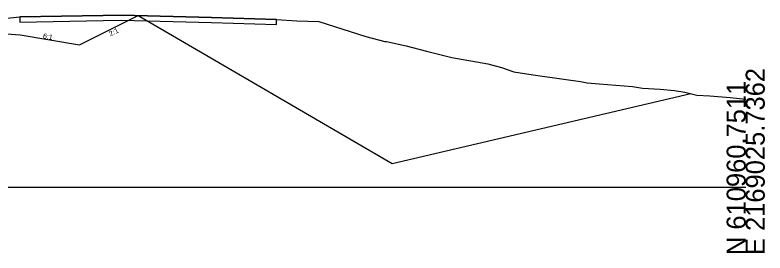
# Model space of a CAD drawing. Extents: x -26 to 1303, y -3010 to 12033.
# Drawn here: x 1192.5 to 1302.8, y 8990.3 to 9025.3 of the extents above; entities that cross this region are included whole.
import ezdxf

# ---------------------------------------------------------------- set-up
doc = ezdxf.new("R2010")
doc.units = 0
for name, color, linetype in [('RD_GPK_XS_Cell', 7, 'Continuous'), ('RD_Sketch10', 7, 'Continuous'), ('RD_XS_ExGround', 7, 'Continuous'), ('RD_XS_ExPaveRet', 7, 'Continuous'), ('RD_XS_Greenside', 7, 'Continuous'), ('RD_XS_TieSlope', 7, 'Continuous'), ('RD_XS_TX_Slope', 7, 'Continuous')]:
    doc.layers.add(name, color=color, linetype=linetype)

msp = doc.modelspace()

# ---------------------------------------------------------------- linework, layer by layer
at = {"layer": 'RD_GPK_XS_Cell'}
msp.add_line((1150, 9000), (1300, 9000), dxfattribs=at)
at = {"layer": 'RD_Sketch10'}
msp.add_lwpolyline([(1210.65, 9025.2), (1248.02, 9003.44), (1291.93, 9013.73)], dxfattribs=at)
at = {"layer": 'RD_XS_ExGround'}
msp.add_lwpolyline([(1186.62, 9024.32), (1193.26, 9024.98), (1205.52, 9025.21), (1208.25, 9025.26), (1221.44, 9024.91), (1230.99, 9024.63), (1233.96, 9024.42), (1237.23, 9024.31), (1244.12, 9022.13), (1246.91, 9021.36), (1247.15, 9021.36), (1250.05, 9020.73), (1253.07, 9019.97), (1256.77, 9019.02), (1262.09, 9018.09), (1264.08, 9017.56), (1265.88, 9016.94), (1268.74, 9016.5), (1273.23, 9015.82), (1275.69, 9015.5), (1276.68, 9015.28), (1278.46, 9015.18), (1283.36, 9014.76), (1284.82, 9014.5), (1287.42, 9014.38), (1289.52, 9014.17), (1291.06, 9013.95), (1292.81, 9013.5), (1294.74, 9013.4), (1297.74, 9013.13), (1300, 9012.91)], dxfattribs=at)
at = {"layer": 'RD_XS_ExPaveRet'}
for points in [[(1230.99, 9024.63), (1221.44, 9024.91), (1221.44, 9024.91), (1208.25, 9025.26), (1208.25, 9025.26), (1208.25, 9025.26), (1205.52, 9025.21), (1205.52, 9025.21), (1193.26, 9024.98), (1193.26, 9024.98), (1193.26, 9024.98), (1193.26, 9024.23), (1193.26, 9024.23), (1205.52, 9024.46), (1205.52, 9024.46), (1208.25, 9024.51), (1208.25, 9024.51), (1208.25, 9024.51), (1221.44, 9024.16), (1221.44, 9024.16), (1230.99, 9023.88), (1230.99, 9023.88), (1230.99, 9024.63), (1230.99, 9024.63), (1230.99, 9024.63)], [(1230.99, 9024.63), (1221.44, 9024.91), (1208.25, 9025.26), (1205.52, 9025.21), (1193.26, 9024.98), (1193.26, 9024.98), (1193.26, 9024.23), (1193.26, 9024.23), (1205.52, 9024.46), (1208.25, 9024.51), (1221.44, 9024.16), (1230.99, 9023.88), (1230.99, 9024.63)]]:
    msp.add_lwpolyline(points, dxfattribs=at)
at = {"layer": 'RD_XS_Greenside'}
for p, q in [((1202.03, 9020.89), (1210.65, 9025.2)), ((1193.3, 9022.34), (1202.03, 9020.89))]:
    msp.add_line(p, q, dxfattribs=at)
at = {"layer": 'RD_XS_TieSlope'}
msp.add_line((1191.3, 9022.5), (1193.3, 9022.34), dxfattribs=at)

# ---------------------------------------------------------------- texts
at = {"layer": 'RD_GPK_XS_Cell'}
for s, p in [('E 2169025.7362', (1302.8, 8990)), ('N 610960.7511', (1300, 8990))]:
    msp.add_text(s, height=2.8, rotation=90, dxfattribs=at).set_placement(p)
at = {"layer": 'RD_XS_TX_Slope'}
for s, rotation, p in [('6:1', 350.5377, (1196.6, 9021.85)), ('2:1', 26.5651, (1206.57, 9022.11))]:
    msp.add_text(s, height=0.75, rotation=rotation, dxfattribs=at).set_placement(p)

doc.saveas('drawing.dxf')
